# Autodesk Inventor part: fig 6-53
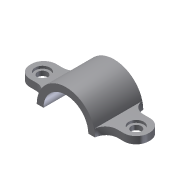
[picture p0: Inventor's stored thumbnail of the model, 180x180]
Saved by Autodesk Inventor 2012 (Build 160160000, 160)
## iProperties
Created: 2004-05
Part Number: fig 6-53
Document SubType Name: Modeling
Designer: CADCIM Technologies
Manufacturer: Standard
Standards Organization: Custom
Density: 1 g/cm^3
Material: Default
Author: CADCIM Technologies
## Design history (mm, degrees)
node "Sketch1"
sketch "Sketch2"
  geometry: L1 (23.378, 0)-(17.996, 0); L2 (-17.996, 0)-(-23.378, 0); A1 r 23.378 centre (0, 0) between (23.378, 0) and (-23.378, 0); A2 r 17.996 centre (0, 0) between (17.996, 0) and (-17.996, 0)
  constraints: 4 end point, 4 point on circle, 2 centre point, 1 collinear, 1 horizontal
extrude "Extrusion1" new body sketch "Sketch2" stored distance "d0" = 38.75; taper "d1" = 0 deg
sketch "Sketch3"
  geometry: L1 (23.378, 0)-(17.996, 0); L2 (-17.996, 0)-(-23.378, 0) reference; L3 (-23.378, 0)-(-47.662, 0); L4 (-47.662, 0)-(-47.662, 5.722); L5 (-47.662, 5.722)-(-22.667, 5.722); A1 r 17.996 centre (0, 0) between (17.996, 0) and (-17.996, 0) reference; A2 r 23.378 centre (0, 0) between (23.378, 0) and (-23.378, 0) reference; 1 further point
  constraints: 10 end point, 5 point on circle, 2 centre point, 1 collinear, 1 horizontal, 1 midpoint, 1 parallel, 1 perpendicular, 3 other
extrude "Extrusion2" join sketch "Sketch3" stored distance "d2" = 21; taper "d3" = 0 deg
fillet "Fillet1" dims "d4" = 10
hole "Hole1" diameter "d7" = 8; stored, may be unused: countersink angle "d11" = 90 deg, drill point angle "d13" = 118 deg; dims "d5" = 10, "d6" = 10, "d8" = 6, "d9" = 12, "d10" = 2, "d12" = 12
fillet "Fillet2" dims "d14" = 9.5
mirror "Mirror1"
body "Solid1"
